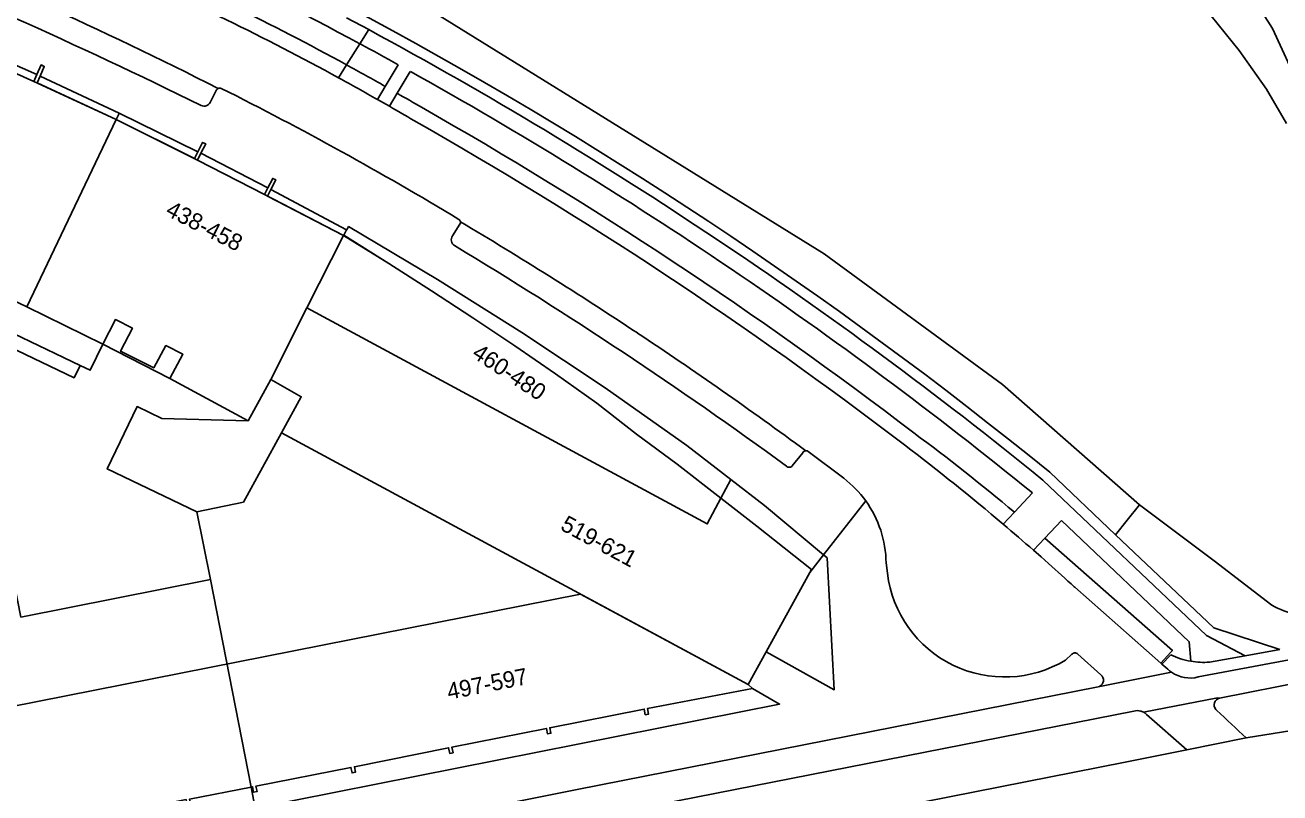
# Model space of a CAD drawing. Extents: x 194485 to 197793, y 468269 to 470822.
# Drawn here: x 195096.6 to 195187.3, y 469480.3 to 469535.8 of the extents above; entities that cross this region are included whole.
import ezdxf

# ---------------------------------------------------------------- set-up
doc = ezdxf.new("R2010")
doc.units = 0
for name, color, linetype in [('BGT begrenzing pand op maaiveld onder overbouw', 7, 'Continuous'), ('BGT grensvlak begroeid terreindeel LR', 7, 'Continuous'), ('BGT grensvlak kunstwerkdeel plus 1', 7, 'Continuous'), ('BGT grensvlak onbegroeid terreindeel', 7, 'Continuous'), ('BGT grensvlak pand deel overbouw', 7, 'Continuous'), ('BGT grensvlak pand min 1', 7, 'Continuous'), ('BGT grensvlak pand op maaiveld', 7, 'Continuous'), ('BGT grensvlak pand op maaiveld LR', 7, 'Continuous'), ('BGT grensvlak vegetatieobject', 7, 'Continuous'), ('BGT grensvlak vegetatieobject LR', 7, 'Continuous'), ('BGT grensvlak waterdeel', 7, 'Continuous'), ('BGT grensvlak wegdeel', 7, 'Continuous'), ('BGT tekst huisnummerreeks', 7, 'Continuous')]:
    doc.layers.add(name, color=color, linetype=linetype)

msp = doc.modelspace()

# ---------------------------------------------------------------- linework, layer by layer
at = {"layer": 'BGT begrenzing pand op maaiveld onder overbouw'}
for p, q in [((195119.627, 469520.659), (195119.601, 469520.616)), ((195150.152, 469490.506), (195153.309, 469496.242))]:
    msp.add_line(p, q, dxfattribs=at)
for points in [[(195097.452, 469532.256), (195097.233, 469531.758), (195092.257, 469534.001), (195092.472, 469534.476)], [(195103.19, 469529.011), (195097.462, 469531.657), (195097.68, 469532.153)], [(195109.083, 469526.681), (195108.833, 469526.194), (195103.19, 469529.011)], [(195114.148, 469524.077), (195113.899, 469523.592), (195109.056, 469526.079), (195109.307, 469526.568)], [(195119.601, 469520.616), (195114.121, 469523.478), (195114.369, 469523.961)], [(195146.886, 469501.625), (195143.731, 469504.078), (195140.792, 469506.254), (195137.918, 469508.505), (195134.938, 469510.612), (195131.986, 469512.655), (195128.955, 469514.68), (195125.967, 469516.634), (195122.891, 469518.609), (195119.627, 469520.659)], [(195102.216, 469512.777), (195103.125, 469514.545), (195104.352, 469513.914), (195103.497, 469512.251), (195105.903, 469511.048), (195106.779, 469512.668), (195108.007, 469512.037), (195107.06, 469510.286)], [(195153.309, 469496.242), (195153.432, 469496.466), (195149.478, 469499.61), (195146.886, 469501.625)], [(195112.936, 469480.736), (195113.035, 469480.756), (195113.115, 469480.354), (195113.36, 469480.402), (195113.281, 469480.805), (195120.148, 469482.161), (195120.227, 469481.759), (195120.472, 469481.807), (195120.393, 469482.209), (195127.203, 469483.574), (195127.284, 469483.172), (195127.529, 469483.221), (195127.449, 469483.623), (195134.273, 469484.976), (195134.353, 469484.574), (195134.598, 469484.623), (195134.518, 469485.025), (195141.338, 469486.371), (195141.417, 469485.969), (195141.662, 469486.017), (195141.583, 469486.42), (195149.172, 469487.871)]]:
    msp.add_lwpolyline(points, dxfattribs=at)
at = {"layer": 'BGT grensvlak begroeid terreindeel LR'}
for p, q in [((195119.818, 469532.973), (195120.786, 469534.497)), ((195170.645, 469503.499), (195175.406, 469498.979)), ((195175.406, 469498.979), (195182.496, 469492.248)), ((195182.496, 469492.248), (195187.281, 469490.689))]:
    msp.add_line(p, q, dxfattribs=at)
msp.add_lwpolyline([(195175.406, 469498.979), (195176.252, 469500.046), (195177.122, 469501.144)], dxfattribs=at)
msp.add_arc((194972.758, 469260.453), 313.418, 50.84769, 73.19, dxfattribs=at)
at = {"layer": 'BGT grensvlak kunstwerkdeel plus 1'}
msp.add_lwpolyline([(195187.753, 469528.729), (195186.298, 469531.2), (195184.335, 469534.013), (195182.319, 469536.508), (195179.613, 469539.481), (195177.491, 469541.604), (195175.342, 469543.236), (195173.57, 469544.247), (195174.59, 469548.481), (195177.683, 469546.115), (195180.411, 469543.81), (195182.503, 469541.808), (195184.567, 469539.013), (195186.742, 469535.589), (195188.692, 469531.356)], dxfattribs=at)
at = {"layer": 'BGT grensvlak onbegroeid terreindeel'}
msp.add_line((195100.576, 469511.232), (195091.106, 469515.768), dxfattribs=at)
at = {"layer": 'BGT grensvlak pand deel overbouw'}
for p, q in [((195097.452, 469532.256), (195092.472, 469534.476)), ((195103.41, 469529.472), (195097.68, 469532.153)), ((195109.083, 469526.681), (195103.41, 469529.472)), ((195114.148, 469524.077), (195109.307, 469526.568)), ((195119.816, 469521.042), (195114.369, 469523.961)), ((195119.816, 469521.042), (195119.627, 469520.659)), ((195102.216, 469512.777), (195107.06, 469510.286)), ((195146.886, 469501.625), (195147.604, 469502.969))]:
    msp.add_line(p, q, dxfattribs=at)
for points in [[(195103.19, 469529.011), (195103.401, 469529.454), (195103.41, 469529.472)], [(195147.604, 469502.969), (195144.42, 469505.435), (195138.519, 469509.61), (195132.491, 469513.602), (195126.394, 469517.446), (195119.982, 469521.268), (195119.839, 469521.03), (195119.816, 469521.042)], [(195147.604, 469502.969), (195150.026, 469501.093), (195154.307, 469497.525)], [(195154.307, 469497.525), (195154.567, 469497.308), (195155.079, 469487.777), (195150.152, 469490.506)], [(195149.172, 469487.871), (195151.123, 469486.737), (195113.238, 469479.216), (195112.936, 469480.736)]]:
    msp.add_lwpolyline(points, dxfattribs=at)
at = {"layer": 'BGT grensvlak pand min 1'}
msp.add_lwpolyline([(195092.257, 469534.001), (195097.233, 469531.758), (195103.19, 469529.011), (195109.056, 469526.079), (195113.899, 469523.592), (195119.601, 469520.616), (195122.891, 469518.609), (195125.967, 469516.634), (195128.955, 469514.68), (195131.986, 469512.655), (195134.938, 469510.612), (195137.918, 469508.505), (195140.792, 469506.254), (195143.731, 469504.078), (195146.886, 469501.625), (195149.478, 469499.61), (195153.432, 469496.466), (195148.852, 469488.143), (195136.748, 469494.684), (194989.988, 469465.668)], dxfattribs=at)
at = {"layer": 'BGT grensvlak pand op maaiveld'}
for p, q in [((195091.176, 469518.074), (195096.714, 469515.472)), ((195096.714, 469515.472), (195102.216, 469512.777)), ((195107.06, 469510.286), (195112.715, 469507.23)), ((195112.715, 469507.23), (195114.357, 469510.207)), ((195109.012, 469500.645), (195109.994, 469495.738)), ((195148.852, 469488.143), (195150.152, 469490.506)), ((195149.172, 469487.871), (195148.852, 469488.143))]:
    msp.add_line(p, q, dxfattribs=at)
for points in [[(195097.68, 469532.153), (195097.99, 469532.856), (195097.761, 469532.957), (195097.452, 469532.256)], [(195109.307, 469526.568), (195109.654, 469527.245), (195109.432, 469527.359), (195109.083, 469526.681)], [(195114.369, 469523.961), (195114.72, 469524.643), (195114.498, 469524.757), (195114.148, 469524.077)], [(195115.135, 469506.364), (195116.561, 469508.965), (195114.357, 469510.207)], [(195115.135, 469506.364), (195112.374, 469501.328), (195109.012, 469500.645)], [(195072.093, 469488.252), (195071.12, 469493.156), (195080.835, 469495.084), (195081.848, 469489.991), (195086.615, 469490.924), (195085.615, 469496.027), (195095.336, 469497.932), (195096.298, 469493.025), (195109.994, 469495.738)], [(195093.387, 469476.886), (195094.101, 469477.028), (195094.181, 469476.625), (195094.426, 469476.673), (195094.346, 469477.077), (195098.809, 469477.961), (195098.889, 469477.558), (195099.134, 469477.607), (195099.054, 469478.01), (195103.518, 469478.894), (195103.598, 469478.492), (195103.843, 469478.54), (195103.763, 469478.943), (195108.23, 469479.828), (195108.314, 469479.405), (195108.559, 469479.453), (195108.48, 469479.856), (195112.936, 469480.736)]]:
    msp.add_lwpolyline(points, dxfattribs=at)
at = {"layer": 'BGT grensvlak pand op maaiveld LR'}
for p, q in [((195103.19, 469529.011), (195096.714, 469515.472)), ((195119.601, 469520.616), (195116.969, 469515.391)), ((195116.969, 469515.391), (195114.357, 469510.207)), ((195115.135, 469506.364), (195148.852, 469488.143)), ((195109.994, 469495.738), (195112.936, 469480.736))]:
    msp.add_line(p, q, dxfattribs=at)
msp.add_lwpolyline([(195116.969, 469515.391), (195145.891, 469499.762), (195146.886, 469501.625)], dxfattribs=at)
at = {"layer": 'BGT grensvlak vegetatieobject'}
msp.add_lwpolyline([(195178.674, 469489.702), (195179.396, 469490.49), (195179.506, 469490.611), (195170.285, 469498.731)], dxfattribs=at)
for centre, radius, start, end in [((195022.687, 469355.43), 202.376, 61.3175, 66.51568), ((195030.626, 469369.8), 185.959, 60.34806, 61.33843), ((195027.856, 469364.519), 191.919, 59.50695, 60.1107), ((194970.154, 469256.879), 313.99, 52.60929, 60.4009), ((195074.23, 469389.033), 145.812, 49.92799, 53.56784)]:
    msp.add_arc(centre, radius, start, end, dxfattribs=at)
at = {"layer": 'BGT grensvlak vegetatieobject LR'}
msp.add_line((195119.26, 469532.024), (195119.818, 469532.973), dxfattribs=at)
at = {"layer": 'BGT grensvlak waterdeel'}
for points in [[(194822.494, 469649.692), (194848.181, 469632.596), (194861.722, 469624.726), (194876.54, 469618.509), (194928.873, 469602.517), (194938.02, 469600.088), (194982.982, 469586.61), (195000, 469581.494), (195006.376, 469579.649), (195060.365, 469563.684), (195090.937, 469553.27), (195126.606, 469536.49), (195154.352, 469519.31), (195167.226, 469509.857), (195177.122, 469501.144)], [(195186.687, 469493.891), (195182.529, 469497.084), (195177.122, 469501.144)]]:
    msp.add_lwpolyline(points, dxfattribs=at)
msp.add_arc((195189.989, 469499.794), 6.764, 240.78001, 257.10212, dxfattribs=at)
at = {"layer": 'BGT grensvlak wegdeel'}
for p, q in [((195119.833, 469536.37), (195121.431, 469535.512)), ((195120.786, 469534.497), (195121.431, 469535.512)), ((195120.786, 469534.497), (195120.811, 469534.483)), ((195122.625, 469531.407), (195123.565, 469532.977)), ((195123.494, 469530.911), (195124.439, 469532.492)), ((195109.983, 469530.249), (195110.442, 469531.155)), ((195122.06, 469530.463), (195122.625, 469531.407)), ((195122.929, 469529.967), (195123.494, 469530.911)), ((195128.02, 469521.442), (195127.475, 469520.593)), ((195152.795, 469504.908), (195152.043, 469503.974)), ((195155.768, 469503.064), (195153.188, 469505.004)), ((195181.98, 469491.704), (195170.149, 469502.935)), ((195169.392, 469502.005), (195168.096, 469500.614)), ((195154.307, 469497.525), (195157.347, 469501.433)), ((195168.096, 469500.614), (195167.284, 469499.743)), ((195171.487, 469500.011), (195170.285, 469498.731)), ((195170.285, 469498.731), (195169.467, 469497.861)), ((195153.309, 469496.242), (195154.307, 469497.525)), ((195158.914, 469496.193), (195158.818, 469496.948)), ((195172.42, 469495.212), (195172.452, 469495.182)), ((195172.452, 469495.182), (195178.674, 469489.702)), ((195184.771, 469490.237), (195181.98, 469491.704)), ((195172.235, 469490.339), (195171.786, 469489.915)), ((195174.34, 469488.848), (195172.665, 469490.354)), ((195179.386, 469490.304), (195178.757, 469489.629)), ((195184.771, 469490.237), (195182.182, 469489.772)), ((195187.281, 469490.689), (195184.771, 469490.237)), ((195178.674, 469489.702), (195178.757, 469489.629)), ((195178.757, 469489.629), (195179.177, 469489.259)), ((195187.942, 469489.925), (195181.374, 469488.696)), ((195179.454, 469489.034), (195174.138, 469487.974)), ((195182.918, 469487.167), (195189.247, 469488.419)), ((195174.138, 469487.974), (195136.505, 469480.557)), ((195174.138, 469487.974), (195174.23, 469488.013)), ((195177.409, 469486.153), (195182.775, 469487.186)), ((195182.918, 469487.167), (195182.775, 469487.186)), ((195180.542, 469483.429), (195177.646, 469485.985)), ((195191.826, 469485.441), (195184.838, 469484.284)), ((195184.838, 469484.284), (195180.542, 469483.429)), ((195180.542, 469483.429), (195176.106, 469482.546)), ((195176.106, 469482.546), (195127.009, 469472.851)), ((195136.505, 469480.557), (195079.679, 469469.291))]:
    msp.add_line(p, q, dxfattribs=at)
for points in [[(195122.06, 469530.463), (195122.495, 469530.216), (195122.929, 469529.967)], [(195100.576, 469511.232), (195100.144, 469510.331), (195090.674, 469514.866), (195091.106, 469515.768)], [(195102.216, 469512.777), (195101.308, 469510.882), (195100.576, 469511.232)], [(195109.012, 469500.645), (195102.535, 469503.747), (195104.694, 469508.255), (195106.489, 469507.395), (195112.715, 469507.23)], [(195180.831, 469489.83), (195180.722, 469491.244), (195171.487, 469500.011)], [(195169.467, 469497.861), (195170.017, 469497.377), (195170.563, 469496.892)], [(195048.78, 469460.887), (195087.977, 469468.689), (195136.87, 469478.383), (195176.73, 469486.234)], [(195182.71, 469486.28), (195182.675, 469486.31), (195182.642, 469486.343)]]:
    msp.add_lwpolyline(points, dxfattribs=at)
for centre, radius, start, end in [((194970.157, 469254.305), 318.114, 61.7379, 72.03179), ((194972.904, 469260.727), 303.537, 63.03386, 68.35967), ((194943.013, 469193.789), 375.116, 63.68293, 68.24157), ((195022.551, 469355.172), 201.567, 61.32867, 66.52074), ((194972.813, 469260.54), 312.565, 50.85052, 61.60936), ((194989.972, 469291.948), 275.576, 61.00205, 61.65466), ((194990.451, 469297.684), 267.408, 60.5169, 61.20377), ((194972.819, 469260.543), 311.36, 50.85107, 60.85891), ((195110.657, 469531.049), 0.24, 117.31935, 153.76167), ((195110.665, 469531.035), 0.256, 63.92452, 117.5636), ((194998.36, 469307.354), 250.548, 58.85648, 63.34035), ((195109.537, 469530.474), 0.499, 243.71589, 333.25705), ((195024.958, 469359.409), 196.693, 59.52997, 60.12636), ((194970.161, 469256.898), 312.87, 52.60823, 60.40035), ((195127.796, 469521.568), 0.265, 10.53101, 57.45144), ((195127.801, 469521.579), 0.258, 327.86815, 8.1223), ((194971.489, 469258.42), 306.245, 56.42529, 59.25287), ((195127.898, 469520.323), 0.502, 147.39868, 238.69829), ((194959.006, 469240.303), 326.508, 53.8467, 58.90443), ((194971.971, 469259.355), 305.199, 53.6156, 56.40352), ((195054.046, 469366.182), 175.104, 49.70755, 52.70087), ((195153.028, 469504.801), 0.257, 92.96002, 155.25741), ((195153.03, 469504.796), 0.262, 52.73824, 93.196), ((195151.821, 469504.131), 0.272, 224.92259, 324.74213), ((195150.994, 469496.862), 7.827, 35.73315, 52.4107), ((195150.986, 469496.863), 7.833, 0.62308, 35.69406), ((195052.738, 469364.669), 177.104, 48.76861, 49.70107), ((195012.219, 469319.999), 237.411, 47.56265, 48.167), ((195167.385, 469497.226), 8.533, 186.95232, 301.04835), ((195172.457, 469490.137), 0.301, 46.31086, 137.6849), ((195181.732, 469495.018), 5.266, 243.53613, 260.14202), ((195180.726, 469490.883), 2.244, 226.35262, 235.47524), ((195181.733, 469495.071), 5.318, 260.23773, 274.84574), ((195174.046, 469488.462), 0.485, 292.33495, 52.65559), ((195180.78, 469490.944), 2.325, 235.2266, 284.80511), ((195183.016, 469486.676), 0.501, 101.31171, 221.6516), ((195176.958, 469485.325), 0.937, 74.26359, 104.07233), ((195176.961, 469485.261), 0.998, 63.36256, 75.46161), ((195176.981, 469485.298), 0.956, 45.92764, 63.4097), ((194934.264, 469219.271), 364.718, 46.60411, 47.06246)]:
    msp.add_arc(centre, radius, start, end, dxfattribs=at)

# ---------------------------------------------------------------- texts
at = {"layer": 'BGT tekst huisnummerreeks'}
for s, rotation, p in [('438-458', 332.8, (195106.674, 469522.132)), ('460-480', 326.5, (195128.814, 469511.88)), ('519-621', 331.6, (195135.207, 469499.382)), ('497-597', 11.2, (195127.22, 469487.045))]:
    msp.add_text(s, height=1.2, rotation=rotation, dxfattribs=at).set_placement(p)

doc.saveas('drawing.dxf')
